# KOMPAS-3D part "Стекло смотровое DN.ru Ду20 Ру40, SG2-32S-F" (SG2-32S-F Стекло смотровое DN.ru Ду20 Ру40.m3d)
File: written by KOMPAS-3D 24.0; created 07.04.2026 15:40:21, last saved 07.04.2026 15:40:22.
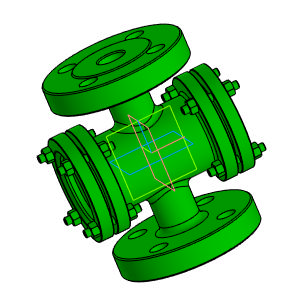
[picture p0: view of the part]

Document properties: Автор: Main; Полное имя файла: D:\DN.ru Аутсерс\Стекло смотровое DN.ru\SG2-32S-F Стекло смотровое DN.ru Ду20 Ру40\SG2-32S-F Стекло смотровое DN.ru Ду20 Ру40.m3d

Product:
- Body: Тело 1  | qty 1
    Масса: 3.869459
- Part/product: Стекло смотровое DN.ru Ду20 Ру40  | designation SG2-32S-F
    Масса: 4.8
    Раздел спецификации: Прочие изделия
    Примечание: D500-00104

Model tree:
1. Операция без истории:1

Expressions: SG2-32S-F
